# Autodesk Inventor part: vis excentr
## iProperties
Created: 2009-10
Part Number: vis excentr
Document SubType Name: Modeling
Designer: Olivier
Density: 1 g/cm^3
Author: Olivier
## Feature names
1. Extrusion1
2. Révolution1 [Revolution]
3. Extrusion2
4. Chanfrein1 [Chamfer]
